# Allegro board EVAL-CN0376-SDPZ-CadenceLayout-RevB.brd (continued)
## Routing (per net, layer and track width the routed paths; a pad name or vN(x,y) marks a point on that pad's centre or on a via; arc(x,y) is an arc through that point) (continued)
UNNAMED_3_AD71244_I22_REFIN1: length 5.5
  TOP w0.279: C26.2 80.51,43.81 U5.13
  TOP w0.305: C26.2 82.51,44.2 C25.2 82.93,44.62 R24.2
UNNAMED_3_AD71244_I22_REFIN1_1: length 5.5
  TOP w0.279: C26.1 80.51,43.31 U5.12
  TOP w0.305: R23.2 82.93,42.51 C24.1 82.51,42.93 C26.1
UNNAMED_3_AD71244_I22_REGCAPA: length 2.4
  TOP w0.279: 74.8,46.86 74.96,46.71 U5.24
  TOP w0.305: C38.2 74.04,47.62 74.8,46.86
UNNAMED_3_AD71244_I22_REGCAPD: length 2.7
  TOP w0.279: U5.1 74.96,40.54 74.68,40.26 74.04,40.26 C37.2
UNNAMED_3_ADUM5010_I79_GNDISO1: length 16.6
  TOP w0.305: v1(59.82,43.05) 59.82,44.83 59.57,45.07 U4.19 ; v1(59.82,43.05) 59.82,42.67 59.62,42.47 U4.15 ; v1(59.82,43.05) 59.75,43.12 U4.16 ; U4.11 59.19,39.87 v1(59.82,39.24) C30.2 E11.2 62.26,39.51 62.23,39.54 R29.2
  BOTTOM w0.305: v1(59.82,39.24) v1(59.82,43.05)
UNNAMED_3_ADUM5010_I79_VISO: length 7.7
  TOP w0.305: v1(60.83,39.5) 60.83,40 R30.2 60.31,40.52 U4.12 ; C30.1 61.11,37.21 v1(61.37,36.96) 61.49,36.83 E10.2
  BOTTOM w0.305: v1(61.37,36.96) 61.37,38.96 v1(60.83,39.5)
UNNAMED_3_ADUM5010_I79_VSEL: length 7.3
  TOP w0.305: R28.1 R27.1 R29.1 R30.1 60.22,41.17 U4.13
UNNAMED_3_CAP_I95_N2: length 3.5
  TOP w0.305: R19.2 84.62,49.4 84.49,49.28 C60.2 83.31,48.89 R46.1
UNNAMED_3_CN4P_I61_N1: length 22.3
  TOP w0.305: P2.1 D7.C v1(93.47,37.97) ; R24.1 85.89,45.97 86.36,45.5 R21.2 v1(87.95,43.12)
  BOTTOM w0.305: v1(93.47,37.97) 93.47,39.75 90.11,43.12 v1(87.95,43.12)
UNNAMED_3_CN4P_I61_N2: length 31.6
  TOP w0.279: R20.1 76.96,34.54
  TOP w0.305: P2.2 D8.C v1(93.47,41.78) ; 76.96,34.54 v1(77.72,33.78)
  BOTTOM w0.305: v1(77.72,33.78) 90.36,33.78 94.23,37.66 94.23,41.02 v1(93.47,41.78)
UNNAMED_3_CN4P_I61_N3: length 16.6
  TOP w0.305: v1(93.47,45.59) D9.C P2.3 ; v1(87.5,46.9) 86.65,47.75 R18.1 R19.1
  BOTTOM w0.305: v1(93.47,45.59) 92.16,46.9 v1(87.5,46.9)
UNNAMED_3_CN4P_I61_N4: length 8.1
  TOP w0.305: R16.1 D10.C P2.4
UNNAMED_3_RES_I20_N1: length 18.4
  TOP w0.305: RT2.2 95.78,51.67 95.38,52.07 R26.1 79.76,52.07 79.25,51.56 R25.1
UNNAMED_4_ADP2441_I109_BST: length 2.5
  TOP w0.279: U7.10 28.2,22.78 C45.1
UNNAMED_4_ADP2441_I109_COMP: length 4.5
  TOP w0.279: C43.1 31.53,25.15 U7.2
  TOP w0.305: C42.1 32.55,26.16 C43.1
UNNAMED_4_ADP2441_I109_FB: length 4.6
  TOP w0.279: U7.1 31.53,24.65 R33.2
  TOP w0.305: R34.1 32.55,23.62 R33.2
UNNAMED_4_ADP2441_I109_FREQ: length 2.2
  TOP w0.279: R31.1 28.7,27.85 U7.5
UNNAMED_4_ADP2441_I109_SS: length 2.2
  TOP w0.279: U7.6 28.2,27.84 C44.1
UNNAMED_4_ADP2441_I109_SW: length 12
  TOP w0.279: U7.8 v1(26.16,25.15)
  TOP w0.635: C45.2 24.77,21.59 21.71,24.65 L1.1 v1(23.37,26.03)
  BOTTOM w0.635: v1(23.37,26.03) 25.27,26.03 v1(26.16,25.15)
UNNAMED_4_ADP2441_I109_VCC: length 4.1
  TOP w0.279: U7.11 28.7,21.88 C46.2
  TOP w0.305: C46.2 C47.1
UNNAMED_4_CAP_I209_N2: length 2
  TOP w0.305: R32.1 C42.2
UNNAMED_4_CAP_I219_N1: length 32.7
  TOP w0.305: R34.2 v1(34.25,20.49)
  TOP w0.635: 15.88,28.07 C48.1 14.48,26.98 14.73,26.72 E7.1 ; v1(15.94,26.03) L1.2 ; E7.1 15.67,25.84 ; E7.1 13.79,25.84
  BOTTOM w0.635: v1(15.94,26.03) 17.92,28.02 30.32,28.02 34.25,24.08 v1(34.25,20.49)
UNNAMED_4_CN2P_I225_N1: length 4.5
  TOP w0.889: P3.1 21.72,5.46 20.6,4.34 F1.1
UNNAMED_4_CN2P_I225_N2: length 12.5
  TOP w0.635: D1.1 28.54,11.94 ; D1.1 26.99,13.35 ; D1.1 26.99,10.53 ; E6.1 27.37,16.31 ; E6.1 28.45,15.24 ; E6.1 27.37,14.03 ; 26.54,5.46 25.69,6.31 ; 26.54,5.46 27.39,6.31 ; 26.54,5.46 27.39,4.61 ; 26.54,5.46 25.69,4.61
UNNAMED_4_CN3P_I234_N3: length 26.9
  TOP w0.508: v1(15.75,21.21) DS1.A 16.74,21.91 ; 15.67,23.94 E7.2 14.73,23.06
  BOTTOM w0.508: PWR_SEL.3 17.78,21.21 v1(15.75,21.21)
UNNAMED_4_DIO_I227_N: length 4.7
  TOP w0.635: 18.67,15.74 D2.C 17.51,14.19 ; 20.57,15.24 E5.1 21.53,16.31
UNNAMED_4_DIO_I227_P: length 12.2
  TOP w0.635: D2.A 18.67,8.65 ; D2.A 17.51,10.2 ; D2.A 19.83,10.2 ; D1.2 22.29,13.35 ; D1.2 20.74,11.94 ; D1.2 22.29,10.53 ; F1.2 18.67,8.14 ; F1.2 17.12,7.34 ; F1.2 20.22,7.34
UNNAMED_4_DIOLED_I134_N: length 4.2
  TOP w0.508: DS1.C 18.31,21.91 ; DS1.C R35.1 20.1,20.23 ; DS1.C 18.31,20.51
UNNAMED_5_74LVC2G125_I79_VCC: length 1.8
  TOP w0.279: U9.8 27.4,48.78 27.38,48.77 C64.1
UNNAMED_5_CN120PV4_I1_EEPROMA0: length 17.9
  TOP w0.305: SDP.56 4.53,46.44 5.97,47.88 5.97,49.66 9.74,53.43 R36.1 14.61,53.43 U8.1
UNNAMED_5_CN120PV4_I1_USBVBUS: length 5.6
  TOP w0.356: 4.35,15.85 4.2,15.85 4.19,15.84 SDP.5
  TOP w0.508: v1(5.97,15.84) 4.71,15.84 v1(4.7,15.85) 4.35,15.85
  TOP w1.016: D11.A v1(18.05,18.16) v1(17.4,18.16) v1(16.76,18.16)
  vias: v1(5.33,15.88)
UNNAMED_5_IC24FC256_I3_A1: length 6.2
  TOP w0.305: U8.2 18.11,52.78 18.76,53.43 R38.1 R37.2
VREF1: length 33.5
  TOP w0.279: 75.69,18.16 75.96,17.89 U1.22
  TOP w0.508: C52.2 75.69,18.16
  TOP w0.635: v1(97.66,23.37) 97.77,23.26 RT1.1 ; C52.2 C57.1 75.44,20.83 R39.1 74.04,22.86 REF1.1
  BOTTOM w0.635: v1(97.66,23.37) REF1.1
VREF2: length 33.6
  TOP w0.279: 75.69,46.99 75.96,46.72 U5.22
  TOP w0.508: C53.2 75.69,46.99 ; RT2.1 v1(97.77,52.22)
  TOP w0.635: REF2.1 74.04,51.69 R40.1 75.44,49.66 C61.1 C53.2
  BOTTOM w0.635: REF2.1 89.62,52.2 89.7,52.12 90.39,52.12 90.47,52.2 96.86,52.2 96.88,52.22 v1(97.77,52.22)

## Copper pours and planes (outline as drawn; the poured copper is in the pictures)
+3.3V on TOP: 5.84,4.44 5.71,4.57 5.71,8.64 5.84,8.76 16.51,8.76 16.64,8.89 16.64,17.53 16.51,17.65 18.16,17.65 18.29,17.53 18.29,14.6 17.53,14.6 17.53,10.67 20.19,10.67 20.19,13.95 20.22,13.9 20.28,13.91 20.34,13.97 22.23,13.97 22.23,13.97 22.61,13.97 22.61,9.65 22.72,9.65 22.59,9.52 20.83,9.52 20.83,7.89 20.55,7.62 20.19,7.62 20.19,9.14 17.53,9.14 17.53,7.62 17.14,7.62 17.14,4.95 21.72,4.95 21.72,5.97 20.19,5.97 20.19,6.06 21.65,6.06 21.65,6.54 23.82,6.54 23.82,4.45 24.89,4.45 24.89,9.38 24.99,9.48 25.01,9.59 24.92,9.65 26.54,9.65 26.54,13.97 26.8,13.97 26.8,17.53 26.92,17.65 36.07,17.65 36.2,17.78 36.2,33.27 36.07,33.4 15.88,33.4 15.75,33.53 15.75,44.7 15.88,44.83 26.04,44.83 26.42,45.21 26.42,55.12 26.54,55.24 48.64,55.24 48.77,55.12 48.77,41.4 48.13,41.4 48.13,39.88 48.77,39.88 48.77,11.56 48.13,11.56 48.13,10.03 48.77,10.03 48.77,4.57 48.64,4.44 ; 10 cut-outs
+3.3V on L3_PWR: 5.71,4.57 5.71,8.64 5.84,8.76 19.56,8.76 19.69,8.89 19.69,20.32 19.56,20.45 15.88,20.45 15.75,20.57 15.75,44.7 15.88,44.83 26.04,44.83 26.42,45.21 26.42,55.12 26.54,55.24 48.77,55.24 48.9,55.12 48.9,4.57 48.77,4.44 44.07,4.44 43.94,4.57 43.94,11.3 43.81,11.43 36.96,11.43 36.83,11.3 36.83,4.57 36.7,4.44 5.84,4.44
+3.3VIO on TOP: 5.84,9.52 5.71,9.65 5.71,55.12 5.84,55.24 25.53,55.24 25.65,55.12 25.65,45.72 25.53,45.59 15.11,45.59 14.99,45.47 14.99,32.26 14.86,32.13 13.21,32.13 13.08,32 13.08,22.1 13.33,21.84 14.86,21.84 14.99,21.72 14.99,9.65 14.86,9.52 ; 1 cut-out
+3.3VIO on L3_PWR: 5.71,17.27 5.71,55.12 5.84,55.24 25.53,55.24 25.65,55.12 25.65,45.72 25.53,45.59 15.11,45.59 14.99,45.47 14.99,14.99 14.86,14.86 7.24,14.86 7.11,14.99 7.11,17.02 6.98,17.14 5.84,17.14
AGND1 on BOTTOM (solid shape): outline of 4142 points within 67.06,1.27 102.87,28.57
AGND1 on L3_PWR (solid shape): outline of 2422 points within 67.06,4.44 99.69,25.4
AGND2 on BOTTOM (solid shape): 78.81,39.09 78.91,39.02 78.87,38.91 79.5,37.08 80.13,38.91 80.09,39.02 80.19,39.09 82.21,39.09 82.3,39.03 82.28,38.92 79.08,35.71 75.08,35.71 75.01,35.78 74.93,35.82 74.93,35.94 75.06,36.07 76.58,36.07 76.71,36.19 76.71,36.54 76.71,36.54 76.71,38.84 76.75,38.92 76.84,38.94 77.12,38.94 77.37,39.09
AGND2 on BOTTOM (solid shape): outline of 3934 points within 67.06,30.61 102.87,57.4
AGND2 on L3_PWR (solid shape): outline of 2395 points within 67.06,33.78 99.69,54.23
AGND_A on TOP: 35.81,32.89 35.69,33.02 15.88,33.02 15.75,32.89 15.75,29.84 15.88,29.72 20.7,29.72 20.95,29.46 20.95,22.73 21.08,22.61 21.34,22.61 21.46,22.48 21.46,19.94 21.59,19.81 24.51,19.81 24.64,19.68 24.64,18.29 24.77,18.16 35.69,18.16 35.81,18.29 ; 4 cut-outs
AGND_A on TOP: 1.4,1.27 1.27,1.4 1.27,58.29 1.4,58.42 10.3,58.42 11.43,56.49 12.56,58.42 42.67,58.42 42.67,58.41 44.07,58.41 44.07,58.42 51.69,58.42 51.81,58.29 51.82,58.29 51.82,1.4 51.69,1.27 ; 1 cut-out
AGND_A on BOTTOM: 1.27,1.4 1.27,58.3 1.39,58.42 51.69,58.42 51.82,58.29 51.82,1.4 51.69,1.27 1.4,1.27 ; 1 cut-out
AGND_A on L2_GND: 1.27,1.4 1.27,58.3 1.39,58.42 60.07,58.42 60.2,58.29 60.2,46.35 60.07,46.23 57.4,46.23 57.28,46.1 57.28,33.27 57.4,33.15 60.07,33.15 60.2,33.02 60.2,17.53 60.07,17.4 57.4,17.4 57.28,17.27 57.28,3.94 57.4,3.81 60.07,3.81 60.2,3.68 60.2,1.4 60.07,1.27 1.4,1.27
AGND_A on L3_PWR: 1.27,1.4 1.27,58.3 1.39,58.42 48.77,58.42 48.9,58.29 48.9,56.01 48.77,55.88 3.94,55.88 3.81,55.75 3.81,3.94 3.94,3.81 48.77,3.81 48.9,3.68 48.9,1.4 48.77,1.27 1.4,1.27
AGND_B on TOP (solid shape): 64.87,39.56 65.28,39.56 65.28,39.37 65.79,38.86 66.42,38.86 66.55,38.73 66.55,38.29 65.5,38.29 65.5,37.21 64.78,37.21 64.53,37.47 64.43,37.47 64.43,37.49 63.63,37.49 63.63,37.82 64.43,37.82 64.43,39.14 63.63,39.14 63.63,39.24 63.5,39.37 63.5,39.56 64.54,39.56 64.54,40.64 64.87,40.64
AGND_B on BOTTOM (solid shape): outline of 1167 points within 57.66,30.61 76.33,57.4
AGND_B on L3_PWR (solid shape): outline of 1775 points within 49.53,30.61 102.87,57.4
AGND_B on TOP: 63.88,30.61 63.75,30.73 63.75,33.02 63.88,33.15 100.2,33.15 100.33,33.27 100.33,54.74 100.2,54.86 60.33,54.86 60.2,54.74 60.2,46.35 60.07,46.23 57.78,46.23 57.66,46.35 57.66,57.28 57.78,57.4 95.94,57.4 97.16,56.51 98.37,57.4 102.74,57.4 102.87,57.28 102.87,30.73 102.74,30.61
AGND_B on L2_GND: 100.2,33.15 100.33,33.27 100.33,54.74 100.2,54.86 60.96,54.86 60.83,54.99 60.83,57.28 60.96,57.4 102.74,57.4 102.87,57.28 102.87,30.73 102.74,30.61 63.88,30.61 63.75,30.73 63.75,33.02 63.88,33.15
AVDD1 on L2_GND (solid shape): 72.01,16.38 72.01,15.51 71.94,15.24 72.01,14.97 72.01,12.13 71.43,11.56 72.01,10.98 72.01,8.89 71.88,8.76 67.56,8.76 67.44,8.89 67.44,10.29 67.56,10.41 68.96,10.41 69.09,10.54 69.09,14.95 69.16,15.04 69.27,15.01 70.3,15.36 69.27,15.72 69.16,15.69 69.09,15.78 69.09,16.38 69.22,16.51 71.88,16.51
AVDD2 on L2_GND (solid shape): 72.01,45.21 72.01,40.96 71.43,40.39 72.01,39.81 72.01,37.72 71.88,37.59 67.56,37.59 67.44,37.72 67.44,39.12 67.56,39.24 68.96,39.24 69.09,39.37 69.09,43.62 69.66,44.2 69.09,44.77 69.09,45.21 69.22,45.34 71.88,45.34
DVDD1 on TOP (solid shape): 97.79,14.58 98.52,13.85 99.54,13.94 99.64,13.94 99.69,13.85 99.69,12.31 99.64,12.22 99.54,12.22 98.52,12.31 97.79,11.58 94.62,11.58 94.62,12.51 93.88,12.51 93.88,12.67 93.89,12.69 94.05,13.08 93.89,13.48 93.87,13.59 93.96,13.65 94.62,13.65 94.62,14.58
DVDD1 on TOP (solid shape): 97.79,10.77 98.52,10.04 99.54,10.13 99.64,10.13 99.69,10.04 99.69,8.58 97.72,8.58 97.72,7.77 94.62,7.77 94.62,8.7 94.06,8.7 93.97,8.75 93.97,8.85 93.47,9.72 92.97,8.85 92.97,8.75 92.89,8.7 92.71,8.7 92.71,8.76 92.46,8.76 92.46,9.84 94.62,9.84 94.62,10.77
DVDD1 on TOP (solid shape): 97.79,18.39 98.52,17.66 99.54,17.75 99.64,17.75 99.69,17.66 99.69,16.12 99.64,16.03 99.54,16.03 98.52,16.12 97.79,15.39 94.62,15.39 94.62,16.32 94.06,16.32 93.97,16.37 93.97,16.47 93.47,17.34 92.97,16.47 92.97,16.37 92.89,16.32 92.46,16.32 92.46,17.46 94.62,17.46 94.62,18.39
DVDD1 on TOP (solid shape): 84.02,18.15 84.06,18.23 84.15,18.25 84.33,18.22 84.51,18.25 84.6,18.23 84.64,18.15 84.64,18.13 86.64,18.13 86.83,17.93 86.83,17.92 87.53,17.38 87.94,18.15 87.95,18.2 87.99,18.22 88.26,18.22 88.26,17.46 88.83,17.46 88.83,16.32 88.26,16.32 88.26,16.28 88.22,16.2 88.14,16.18 87.51,15.9 87.6,15.21 87.78,15.04 87.81,14.93 87.72,14.86 87.59,14.84 87.47,14.79 87.37,14.79 87.32,14.87 87.32,15.19 86.77,15.19 86.77,16.85 86.06,17.55 84.9,17.55 84.9,17.81 82.23,17.81 82.23,16.48 82.52,16.48 82.52,16.2 81.97,16.2 81.97,15.86 81.89,15.78 81.56,15.78 81.56,16.07 80.24,16.07 80.24,15.38 79.96,15.38 79.89,15.41 79.86,15.48 79.84,15.61 79.77,15.73 79.85,15.9 79.84,16.09 79.94,16.13 80.02,16.19 81.96,18.13 84.02,18.13
DVDD1 on TOP (solid shape): outline of 410 points within 60.83,4.44 77.21,20.56
DVDD1 on TOP (solid shape): outline of 124 points within 77.37,4.44 99.69,13.83
DVDD1 on TOP (solid shape): outline of 662 points within 60.83,16.47 99.69,25.4
DVDD1 on L2_GND (solid shape): outline of 3748 points within 60.83,4.44 99.69,25.4
DVDD2 on TOP (solid shape): 97.79,39.6 98.52,38.87 99.54,38.96 99.64,38.96 99.69,38.87 99.69,37.4 97.72,37.4 97.72,36.6 94.62,36.6 94.62,37.53 94.06,37.53 93.97,37.58 93.97,37.68 93.47,38.55 92.97,37.68 92.97,37.58 92.89,37.53 92.46,37.53 92.46,38.67 94.62,38.67 94.62,39.25 97.28,39.25 97.28,39.6
DVDD2 on TOP (solid shape): 97.79,47.22 98.52,46.49 99.54,46.58 99.64,46.58 99.69,46.49 99.69,44.95 99.64,44.86 99.54,44.86 98.52,44.95 97.79,44.22 94.62,44.22 94.62,45.15 94.06,45.15 93.97,45.2 93.97,45.3 93.47,46.17 92.97,45.3 92.97,45.2 92.89,45.15 92.46,45.15 92.46,46.29 94.62,46.29 94.62,47.22
DVDD2 on TOP (solid shape): 97.79,43.41 98.52,42.68 99.54,42.77 99.64,42.77 99.69,42.68 99.69,41.14 99.64,41.05 99.54,41.05 98.52,41.14 97.79,40.41 94.62,40.41 94.62,41.34 94.06,41.34 93.97,41.39 93.97,41.49 93.47,42.36 92.97,41.49 92.97,41.39 92.89,41.34 92.46,41.34 92.46,42.48 94.62,42.48 94.62,43.41
DVDD2 on TOP (solid shape): 84.02,47.14 84.06,47.22 84.16,47.23 84.34,47.18 84.52,47.19 84.6,47.17 84.64,47.09 86.74,47.09 86.93,46.9 86.93,46.88 87.56,46.33 88.07,46.99 88.08,47.03 88.12,47.05 88.26,47.05 88.26,46.29 88.83,46.29 88.83,45.15 88.26,45.15 88.26,44.98 88.22,44.9 88.14,44.88 87.51,44.6 87.6,43.92 87.72,43.8 87.75,43.71 87.7,43.63 87.61,43.59 87.54,43.53 87.32,43.53 87.32,44.02 86.77,44.02 86.77,45.67 86.06,46.38 84.9,46.38 84.9,46.64 82.23,46.64 82.23,45.92 82.2,45.85 82.13,45.82 82.09,45.81 82.05,45.79 81.34,45.07 81.32,45.04 81.31,45 81.28,44.93 81.21,44.9 80.24,44.9 80.24,44.21 79.96,44.21 79.89,44.24 79.86,44.31 79.84,44.44 79.77,44.56 79.85,44.73 79.84,44.92 79.94,44.96 80.02,45.02 80.72,45.72 80.83,45.72 81.38,46.27 81.38,46.38 81.96,46.96 84.02,46.96
DVDD2 on TOP (solid shape): outline of 126 points within 77.59,33.78 99.69,42.71
DVDD2 on TOP (solid shape): outline of 424 points within 60.83,33.78 77,49.13
DVDD2 on TOP (solid shape): outline of 764 points within 60.83,44.68 99.69,54.23
DVDD2 on L2_GND (solid shape): outline of 3799 points within 60.83,33.78 99.69,54.23
GND_ISO on TOP (solid shape): 64.23,10.73 65.28,10.73 65.28,10.54 65.79,10.03 66.42,10.03 66.55,9.91 66.55,9.46 65.5,9.46 65.5,8.38 64.73,8.38 64.47,8.64 64.43,8.64 64.43,8.79 63.63,8.79 63.63,9.12 64.43,9.12 64.43,10.44 63.6,10.44 63.5,10.54 63.5,11.68 63.63,11.81 64.23,11.81
GND_ISO on BOTTOM (solid shape): outline of 1154 points within 57.66,1.27 76.33,28.57
GND_ISO on TOP: 63.88,1.27 63.75,1.4 63.75,3.68 63.88,3.81 100.2,3.81 100.33,3.94 100.33,25.91 100.2,26.03 60.32,26.03 60.2,25.91 60.2,17.53 60.07,17.4 60.07,17.4 57.78,17.4 57.66,17.53 57.66,28.45 57.78,28.57 102.74,28.57 102.87,28.45 102.87,1.4 102.74,1.27 98.09,1.27 97.16,3.24 96.22,1.27
GND_ISO on L2_GND: 60.96,28.57 102.74,28.57 102.87,28.45 102.87,1.4 102.74,1.27 63.88,1.27 63.75,1.4 63.75,3.68 63.88,3.81 100.2,3.81 100.33,3.94 100.33,25.91 100.2,26.03 60.96,26.03 60.83,26.16 60.83,28.45
GND_ISO on L3_PWR: 49.66,1.27 49.53,1.4 49.53,28.45 49.66,28.57 102.74,28.57 102.87,28.45 102.87,1.4 102.74,1.27 63.88,1.27 63.75,1.4 63.75,17.27 63.63,17.4 57.4,17.4 57.28,17.27 57.28,1.4 57.15,1.27 ; 1 cut-out
VCC_PMOD on L2_GND: 36.83,40.13 36.83,36.7 36.96,36.58 42.55,36.58 42.67,36.45 42.67,11.43 42.55,11.3 37.21,11.3 37.08,11.18 37.08,9.02 37.21,8.89 44.96,8.89 45.34,9.27 45.34,40.13 45.21,40.26 36.96,40.26
VCC_PMOD on L3_PWR: 37.34,4.57 37.34,10.79 37.47,10.92 43.31,10.92 43.43,10.79 43.43,4.57 43.31,4.44 37.47,4.44
(no net) on TOP: 65.15,11.81 63.63,11.81 63.5,11.68 63.5,10.54 63.63,10.41 63.63,8.51 63.75,8.38 66.42,8.38 66.55,8.51 66.55,9.91 66.42,10.03 65.79,10.03 65.28,10.54 65.28,11.68
(no net) on TOP: 65.15,40.64 63.63,40.64 63.5,40.51 63.5,39.37 63.63,39.24 63.63,37.34 63.75,37.21 66.42,37.21 66.55,37.34 66.55,38.73 66.42,38.86 65.79,38.86 65.28,39.37 65.28,40.51
(no net) on TOP: 63.88,4.44 63.75,4.57 63.75,17.27 63.63,17.4 60.96,17.4 60.83,17.53 60.83,25.27 60.96,25.4 99.57,25.4 99.69,25.27 99.69,4.57 99.57,4.44 ; 19 cut-outs
(no net) on TOP: 63.88,33.78 63.75,33.91 63.75,46.1 63.63,46.23 60.96,46.23 60.83,46.35 60.83,54.1 60.96,54.23 99.57,54.23 99.69,54.1 99.69,33.91 99.57,33.78 ; 22 cut-outs
(no net) on BOTTOM: 57.66,46.35 57.66,57.28 57.78,57.4 66.29,57.4 66.42,57.28 66.42,45.97 66.55,45.85 74.17,45.85 74.3,45.72 74.3,40.39 74.42,40.26 76.2,40.26 76.33,40.13 76.33,36.7 76.2,36.58 74.42,36.58 74.3,36.45 74.3,30.73 74.17,30.61 63.88,30.61 63.75,30.73 63.75,46.1 63.63,46.23 57.78,46.23
(no net) on BOTTOM: 75.06,30.61 74.93,30.73 74.93,35.94 75.06,36.07 76.58,36.07 76.71,36.19 76.71,40.51 76.58,40.64 75.06,40.64 74.93,40.77 74.93,46.48 74.8,46.61 67.18,46.61 67.06,46.74 67.06,57.28 67.18,57.4 102.74,57.4 102.87,57.28 102.87,30.73 102.74,30.61 ; 1 cut-out
(no net) on BOTTOM: 74.93,7.11 75.06,7.24 76.58,7.24 76.71,7.37 76.71,11.68 76.58,11.81 75.06,11.81 74.93,11.94 74.93,17.65 74.8,17.78 67.18,17.78 67.06,17.91 67.06,28.45 67.18,28.57 102.74,28.57 102.87,28.45 102.87,1.4 102.74,1.27 75.06,1.27 74.93,1.4
(no net) on BOTTOM: 57.66,17.53 57.66,28.45 57.78,28.57 66.29,28.57 66.42,28.45 66.42,17.14 66.55,17.02 74.17,17.02 74.3,16.89 74.3,11.56 74.42,11.43 76.2,11.43 76.33,11.3 76.33,7.87 76.2,7.75 74.42,7.75 74.3,7.62 74.3,1.4 74.17,1.27 63.88,1.27 63.75,1.4 63.75,17.27 63.63,17.4 57.78,17.4
(no net) on L2_GND: 60.83,25.27 60.83,17.53 60.96,17.4 63.63,17.4 63.75,17.27 63.75,4.57 63.88,4.44 99.57,4.44 99.69,4.57 99.69,25.27 99.57,25.4 60.96,25.4 ; 1 cut-out
(no net) on L2_GND: 72.01,45.21 71.88,45.34 69.22,45.34 69.09,45.21 69.09,39.37 68.96,39.24 67.56,39.24 67.44,39.12 67.44,37.72 67.56,37.59 71.88,37.59 72.01,37.72
(no net) on L2_GND: 72.01,16.38 71.88,16.51 69.22,16.51 69.09,16.38 69.09,10.54 68.96,10.41 67.56,10.41 67.44,10.29 67.44,8.89 67.56,8.76 71.88,8.76 72.01,8.89
(no net) on L2_GND: 60.83,54.1 60.83,46.35 60.96,46.23 63.63,46.23 63.75,46.1 63.75,33.91 63.88,33.78 99.57,33.78 99.69,33.91 99.69,54.1 99.57,54.23 60.96,54.23 ; 1 cut-out
(no net) on L3_PWR: 74.8,46.61 67.18,46.61 67.06,46.74 67.06,54.1 67.18,54.23 99.57,54.23 99.69,54.1 99.69,33.91 99.57,33.78 75.06,33.78 74.93,33.91 74.93,35.94 75.06,36.07 76.58,36.07 76.71,36.19 76.71,40.51 76.58,40.64 75.06,40.64 74.93,40.77 74.93,46.48
(no net) on L3_PWR: 49.66,30.61 49.53,30.73 49.53,57.28 49.66,57.4 102.74,57.4 102.87,57.28 102.87,30.73 102.74,30.61 63.88,30.61 63.75,30.73 63.75,46.1 63.63,46.23 57.4,46.23 57.28,46.1 57.28,30.73 57.15,30.61 ; 1 cut-out
(no net) on L3_PWR: 74.8,17.78 67.18,17.78 67.06,17.91 67.06,25.27 67.18,25.4 99.57,25.4 99.69,25.27 99.69,4.57 99.57,4.44 75.06,4.44 74.93,4.57 74.93,7.11 75.06,7.24 76.71,7.24 76.84,7.37 76.84,11.81 76.71,11.94 75.06,11.94 74.93,12.06 74.93,17.65
UNNAMED_4_CAP_I219_N1 on TOP: 13.46,25.65 13.59,25.53 16.26,25.53 16.38,25.65 16.38,28.32 16.26,28.45 13.59,28.45 13.46,28.32
UNNAMED_4_CN2P_I225_N2 on TOP: 25.27,9.4 25.15,9.27 25.15,4.19 25.27,4.06 29.84,4.06 29.97,4.19 29.97,16.76 29.84,16.89 27.18,16.89 27.05,16.76 27.05,13.97 26.67,13.59 26.67,9.52 26.54,9.4
UNNAMED_4_CN3P_I234_N3 on TOP: 16.13,22.61 16.13,24.13 16,24.26 13.72,24.26 13.59,24.13 13.59,22.48 13.72,22.35 15.24,22.35 15.37,22.22 15.37,20.95 15.49,20.83 16.89,20.83 17.02,20.95 17.02,22.35 16.89,22.48 16.26,22.48
UNNAMED_4_DIO_I227_N on TOP: 21.97,14.99 21.97,16.51 21.84,16.64 20.7,16.64 20.57,16.51 20.57,16.38 20.45,16.26 16.89,16.26 16.76,16.13 16.76,13.97 16.89,13.84 19.69,13.84 19.81,13.97 19.81,14.73 19.94,14.86 21.84,14.86
UNNAMED_4_DIO_I227_P on TOP: 20.32,10.67 20.19,10.54 16.89,10.54 16.76,10.41 16.76,7.11 16.89,6.98 20.45,6.98 20.57,7.11 20.57,9.78 20.7,9.91 22.48,9.91 22.61,10.03 22.61,13.59 22.48,13.72 20.45,13.72 20.32,13.59
UNNAMED_4_DIOLED_I134_N on TOP (solid shape): 19.18,22.1 19.18,21.59 19.3,21.47 19.3,20.36 20.45,20.36 20.45,20.07 20.32,19.94 18.16,19.94 18.03,20.07 18.03,20.56 18.96,20.56 18.96,21.86 18.03,21.86 18.03,22.1 18.16,22.22 19.05,22.22
UNNAMED_5_CN120PV4_I1_USBVBUS on L3_PWR: 15.88,19.68 16,19.81 19.05,19.81 19.18,19.68 19.18,9.4 19.05,9.27 4.83,9.27 4.44,9.65 4.44,16.38 4.57,16.51 6.1,16.51 6.22,16.38 6.22,14.35 6.35,14.22 15.75,14.22 15.88,14.35

Small or netless copper shapes (teardrops, artwork), in the pictures only: 1 on TOP

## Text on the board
Ref Des/Silkscreen Top: +24V | EVAL-CN0376-SDPZ REV B | GND | EXT | PMOD | CS | SDI | SDO | VCC | SCLK | DGND | RETURN | AIN- | AIN+ | IEXC
DIMENSION: (REF) | NOTES: | 1. THE BOARD SIZE MAY VARY TO COMPENSATE THE COMPONENTS DENSITY OF THE CIRCUIT. | 2. THE BOARD MAY EXTEND TO THE RIGHT AND LOWER PORTION IF THERE IS A NEED TO CHANGE THE BOARD SIZE. | 3. J1 CONNECTOR LOCATION IS FIXED WITH REFERENCE TO THE DISTANCE ON BOARD EDGE ON THE UPPER LEFT PORTION.
PAGE_OUTLINE: J.CHUA | JUN14 | JUN15 | N/A | B | CHANGED AS PER ECR-054029 | J. CHUA
DISPLAY_BOTTOM: L2 GND | 08-      -07
User.6: L3 PWR | 08-      -08
User.7: ROHS COMPLIANCE NOTE: | 100 MICRO INCHES NICKEL/ | 3-5 MICRO INCHES GOLD | HOMOGENOUS MATERIALS IN THIS BOARD SHALL BE COMPLIANT | THE EU RoHS DIRECTIVE 2002/95/EC | 9.3 mils | 36.57 mils
User.22: FIGURE | SIZE | 12.0 | 40.0 | 45.0 | 55.0 | 28.0 | 43.0 | 136.0 | DRILL CHART: TOP to BOTTOM | ALL UNITS ARE IN MILS | TOLERANCE | +3.0/-3.0 | +2.0/-2.0 | PLATED | NON-PLATED | QTY | 502 | 8 | 29 | 1 | 2
